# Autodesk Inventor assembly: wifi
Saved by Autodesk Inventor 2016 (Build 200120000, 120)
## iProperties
Created: 2018-05
Part Number: wifi
Document SubType Name: Assembly
Designer: Administrator
Title: wifi
Author: Administrator
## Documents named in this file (2)
- c:\worker\convert-fusion-mar-2018\tmp\job-1\16\output\files\8c58ff39-88bb-4352-afd9-60265520bae5\wifi.iam
- c:\worker\convert-fusion-mar-2018\tmp\job-1\16\output\files\8c58ff39-88bb-4352-afd9-60265520bae5\Component73.ipt
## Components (1 placed, 1 different names)
1. Component73:1
